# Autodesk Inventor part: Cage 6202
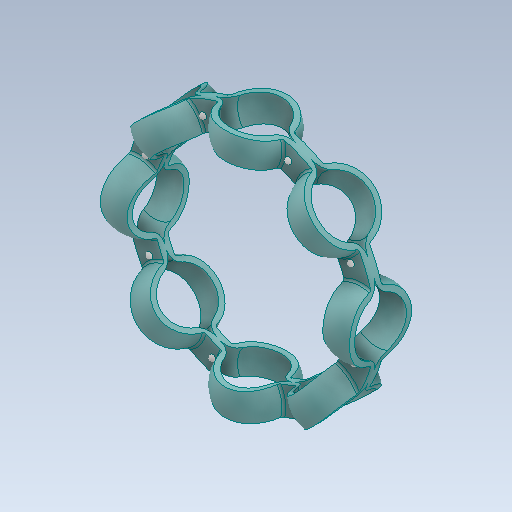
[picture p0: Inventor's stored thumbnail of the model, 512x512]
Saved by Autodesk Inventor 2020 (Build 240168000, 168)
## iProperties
Created: 2001-06
Part Number: Cage 6202
Material: Générique
Document SubType Name: Modeling
Designer: Bruno
Density: 1 g/cm^3
Appearance: Par défaut
Author: Bruno
Sending System: SolidWorks 2011
Last Author: frederic
Last Saved: 2012-02-20
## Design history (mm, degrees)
feature "Bossage-Symétrie1"
node "Solide1"
